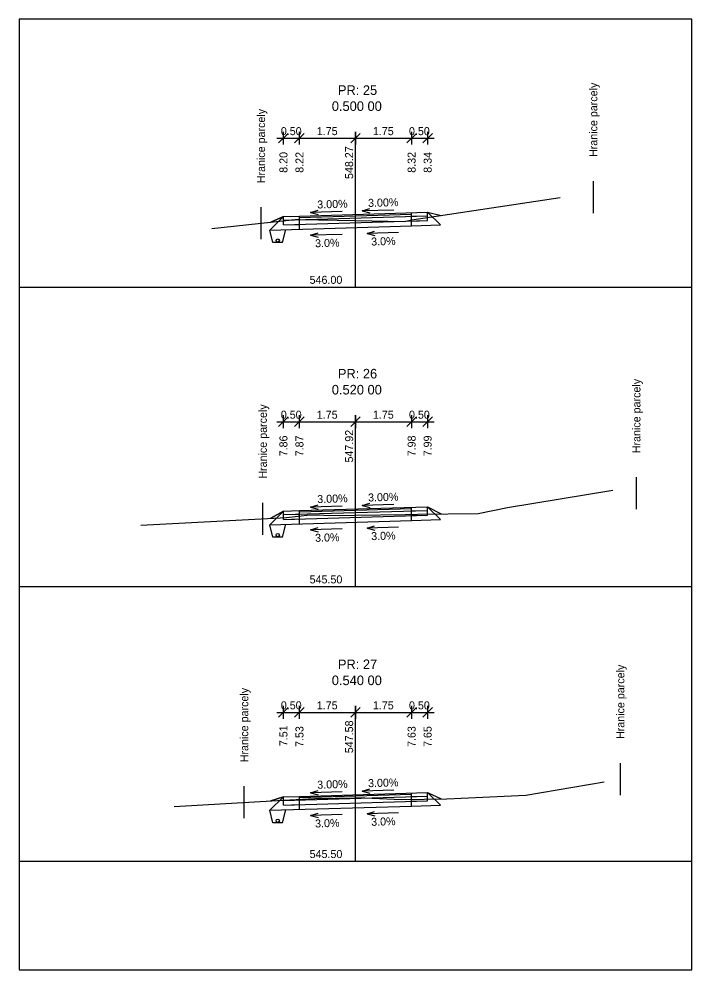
# Model space of a CAD drawing. Extents: x -603737 to -603383, y -1112154 to -1112124.
# Drawn here: x -603504.76 to -603483.76, y -1112153.84 to -1112124.14 of the extents above; entities that cross this region are included whole.
import ezdxf

# ---------------------------------------------------------------- set-up
doc = ezdxf.new("R2010")
doc.units = 0
for name, color, linetype in [('_křivky z hran', 7, 'Continuous'), ('_netisk', 7, 'Continuous'), ('C3D_Podsestava-Popis', 7, 'Continuous'), ('C3D_PP-Popisek', 7, 'Continuous'), ('C3D_PR', 7, 'Continuous'), ('C3D_ZPR', 7, 'Continuous'), ('Default', 7, 'Continuous'), ('konstrukce', 7, 'Continuous')]:
    doc.layers.add(name, color=color, linetype=linetype)

# ---------------------------------------------------------------- blocks, each defined once
blk = doc.blocks.new('_Oblique')
at = {"layer": 'Default'}
blk.add_line((-0.5, -0.5), (0.5, 0.5), dxfattribs=at)
blk = doc.blocks.new('AeccTickLine')
at = {"layer": 'Default'}
blk.add_line((0, 1), (0, -1), dxfattribs=at)

msp = doc.modelspace()

# ---------------------------------------------------------------- linework, layer by layer
at = {"layer": '_netisk'}
msp.add_lwpolyline([(-603504.762, -1112153.84), (-603483.762, -1112153.84), (-603483.762, -1112124.14), (-603504.762, -1112124.14)], close=True, dxfattribs=at)
at = {"layer": 'C3D_Podsestava-Popis'}
for p, q in [((-603496.712, -1112127.861), (-603494.262, -1112127.861)), ((-603494.262, -1112127.861), (-603491.812, -1112127.861)), ((-603494.262, -1112128.243), (-603494.262, -1112128.011)), ((-603496.712, -1112136.717), (-603494.262, -1112136.717)), ((-603494.262, -1112136.717), (-603491.812, -1112136.717)), ((-603494.262, -1112137.443), (-603494.262, -1112136.867)), ((-603496.712, -1112145.794), (-603494.262, -1112145.794)), ((-603494.262, -1112145.794), (-603491.812, -1112145.794)), ((-603494.262, -1112146.364), (-603494.262, -1112145.944))]:
    msp.add_line(p, q, dxfattribs=at)
at = {"layer": 'C3D_PP-Popisek'}
for p, q in [((-603495.665, -1112130.185), (-603495.428, -1112130.109)), ((-603494.681, -1112130.155), (-603495.665, -1112130.185)), ((-603494.054, -1112130.136), (-603493.817, -1112130.061)), ((-603493.07, -1112130.107), (-603494.054, -1112130.136)), ((-603494.054, -1112130.136), (-603493.813, -1112130.197)), ((-603495.665, -1112130.185), (-603495.424, -1112130.246)), ((-603495.665, -1112130.895), (-603495.428, -1112130.819)), ((-603494.681, -1112130.865), (-603495.665, -1112130.895)), ((-603495.665, -1112130.895), (-603495.424, -1112130.956)), ((-603493.9, -1112130.842), (-603493.664, -1112130.767)), ((-603492.917, -1112130.812), (-603493.9, -1112130.842)), ((-603493.9, -1112130.842), (-603493.66, -1112130.903)), ((-603495.665, -1112139.385), (-603495.428, -1112139.31)), ((-603494.681, -1112139.355), (-603495.665, -1112139.385)), ((-603494.054, -1112139.336), (-603493.817, -1112139.261)), ((-603493.07, -1112139.307), (-603494.054, -1112139.336)), ((-603494.054, -1112139.336), (-603493.813, -1112139.397)), ((-603495.665, -1112139.385), (-603495.424, -1112139.446)), ((-603495.665, -1112140.095), (-603495.428, -1112140.02)), ((-603494.681, -1112140.066), (-603495.665, -1112140.095)), ((-603495.665, -1112140.095), (-603495.424, -1112140.156)), ((-603493.9, -1112140.042), (-603493.664, -1112139.967)), ((-603492.917, -1112140.013), (-603493.9, -1112140.042)), ((-603493.9, -1112140.042), (-603493.66, -1112140.103)), ((-603495.665, -1112148.306), (-603495.428, -1112148.231)), ((-603494.681, -1112148.277), (-603495.665, -1112148.306)), ((-603494.054, -1112148.258), (-603493.817, -1112148.182)), ((-603493.07, -1112148.228), (-603494.054, -1112148.258)), ((-603494.054, -1112148.258), (-603493.813, -1112148.319)), ((-603495.665, -1112148.306), (-603495.424, -1112148.367)), ((-603495.665, -1112149.016), (-603495.428, -1112148.941)), ((-603494.681, -1112148.987), (-603495.665, -1112149.016)), ((-603495.665, -1112149.016), (-603495.424, -1112149.077)), ((-603493.9, -1112148.963), (-603493.664, -1112148.888)), ((-603492.917, -1112148.934), (-603493.9, -1112148.963)), ((-603493.9, -1112148.963), (-603493.66, -1112149.025))]:
    msp.add_line(p, q, dxfattribs=at)
at = {"layer": 'C3D_PR'}
for points in [[(-603498.742, -1112130.684), (-603496.141, -1112130.406), (-603496.078, -1112130.403), (-603495.984, -1112130.405), (-603494.262, -1112130.435), (-603492.741, -1112130.461), (-603492.507, -1112130.411), (-603487.876, -1112129.715)], [(-603500.963, -1112139.951), (-603496.414, -1112139.706), (-603495.686, -1112139.628), (-603494.81, -1112139.644), (-603494.262, -1112139.636), (-603492.714, -1112139.616), (-603492.321, -1112139.609), (-603490.432, -1112139.583), (-603489.523, -1112139.397), (-603489.523, -1112139.397), (-603489.522, -1112139.396), (-603486.233, -1112138.855)], [(-603499.917, -1112148.73), (-603496.692, -1112148.549), (-603495.532, -1112148.488), (-603494.262, -1112148.469), (-603493.974, -1112148.465), (-603492.824, -1112148.517), (-603491.407, -1112148.494), (-603488.95, -1112148.382), (-603486.506, -1112147.969)]]:
    msp.add_lwpolyline(points, dxfattribs=at)
at = {"layer": 'C3D_ZPR'}
for p, q in [((-603494.262, -1112132.511), (-603494.262, -1112128.011)), ((-603486.839, -1112130.2), (-603486.839, -1112129.2)), ((-603497.209, -1112131.02), (-603497.209, -1112130.02)), ((-603496.935, -1112130.733), (-603496.512, -1112130.31)), ((-603496.512, -1112130.31), (-603496.907, -1112130.488)), ((-603496.907, -1112130.488), (-603496.512, -1112130.31)), ((-603496.512, -1112130.42), (-603492.012, -1112130.285)), ((-603496.512, -1112130.31), (-603496.012, -1112130.295)), ((-603496.512, -1112130.57), (-603496.512, -1112130.31)), ((-603496.512, -1112130.57), (-603496.512, -1112130.31)), ((-603496.512, -1112130.42), (-603496.012, -1112130.405)), ((-603496.512, -1112130.57), (-603492.012, -1112130.435)), ((-603496.012, -1112130.295), (-603492.012, -1112130.175)), ((-603496.012, -1112130.335), (-603492.512, -1112130.23)), ((-603496.012, -1112130.705), (-603496.012, -1112130.295)), ((-603496.012, -1112130.405), (-603496.012, -1112130.335)), ((-603492.512, -1112130.23), (-603492.512, -1112130.19)), ((-603492.512, -1112130.6), (-603492.512, -1112130.19)), ((-603492.512, -1112130.3), (-603492.012, -1112130.285)), ((-603492.512, -1112130.45), (-603492.512, -1112130.3)), ((-603492.512, -1112130.45), (-603492.012, -1112130.435)), ((-603492.012, -1112130.435), (-603492.012, -1112130.175)), ((-603492.012, -1112130.435), (-603492.012, -1112130.175)), ((-603491.614, -1112130.573), (-603492.012, -1112130.175)), ((-603492.012, -1112130.175), (-603491.587, -1112130.273)), ((-603492.012, -1112130.175), (-603491.587, -1112130.273)), ((-603496.935, -1112130.733), (-603492.512, -1112130.6)), ((-603496.512, -1112130.57), (-603496.012, -1112130.555)), ((-603496.012, -1112130.705), (-603496.012, -1112130.555)), ((-603492.512, -1112130.6), (-603491.614, -1112130.573)), ((-603504.762, -1112132.511), (-603483.762, -1112132.511)), ((-603494.262, -1112141.867), (-603494.262, -1112136.867)), ((-603485.495, -1112139.452), (-603485.495, -1112138.452)), ((-603497.154, -1112140.246), (-603497.154, -1112139.246)), ((-603496.935, -1112139.933), (-603496.512, -1112139.51)), ((-603496.512, -1112139.51), (-603496.907, -1112139.732)), ((-603496.907, -1112139.732), (-603496.512, -1112139.51)), ((-603496.512, -1112139.62), (-603492.012, -1112139.485)), ((-603496.512, -1112139.51), (-603496.012, -1112139.495)), ((-603496.512, -1112139.77), (-603496.512, -1112139.51)), ((-603496.512, -1112139.77), (-603496.512, -1112139.51)), ((-603496.512, -1112139.62), (-603496.012, -1112139.605)), ((-603496.512, -1112139.77), (-603492.012, -1112139.635)), ((-603496.012, -1112139.495), (-603492.012, -1112139.375)), ((-603496.012, -1112139.535), (-603492.512, -1112139.43)), ((-603496.012, -1112139.905), (-603496.012, -1112139.495)), ((-603496.012, -1112139.605), (-603496.012, -1112139.535)), ((-603492.512, -1112139.43), (-603492.512, -1112139.39)), ((-603492.512, -1112139.8), (-603492.512, -1112139.39)), ((-603492.512, -1112139.5), (-603492.012, -1112139.485)), ((-603492.512, -1112139.65), (-603492.512, -1112139.5)), ((-603492.512, -1112139.65), (-603492.012, -1112139.635)), ((-603492.012, -1112139.635), (-603492.012, -1112139.375)), ((-603492.012, -1112139.635), (-603492.012, -1112139.375)), ((-603492.012, -1112139.375), (-603491.614, -1112139.773)), ((-603492.012, -1112139.375), (-603491.587, -1112139.599)), ((-603492.012, -1112139.375), (-603491.587, -1112139.599)), ((-603496.935, -1112139.933), (-603492.512, -1112139.8)), ((-603496.512, -1112139.77), (-603496.012, -1112139.755)), ((-603496.012, -1112139.905), (-603496.012, -1112139.755)), ((-603492.512, -1112139.8), (-603491.614, -1112139.773)), ((-603504.762, -1112141.867), (-603483.762, -1112141.867)), ((-603494.262, -1112150.444), (-603494.262, -1112145.944)), ((-603485.996, -1112148.377), (-603485.996, -1112147.377)), ((-603497.734, -1112149.103), (-603497.734, -1112148.103)), ((-603496.935, -1112148.854), (-603496.512, -1112148.432)), ((-603496.512, -1112148.432), (-603496.907, -1112148.561)), ((-603496.907, -1112148.561), (-603496.512, -1112148.432)), ((-603496.512, -1112148.542), (-603492.012, -1112148.407)), ((-603496.512, -1112148.432), (-603496.012, -1112148.417)), ((-603496.512, -1112148.692), (-603496.512, -1112148.432)), ((-603496.512, -1112148.692), (-603496.512, -1112148.432)), ((-603496.512, -1112148.542), (-603496.012, -1112148.527)), ((-603496.512, -1112148.692), (-603492.012, -1112148.557)), ((-603496.012, -1112148.417), (-603492.012, -1112148.297)), ((-603496.012, -1112148.457), (-603492.512, -1112148.352)), ((-603496.012, -1112148.827), (-603496.012, -1112148.417)), ((-603496.012, -1112148.527), (-603496.012, -1112148.457)), ((-603492.512, -1112148.352), (-603492.512, -1112148.312)), ((-603492.512, -1112148.722), (-603492.512, -1112148.312)), ((-603492.512, -1112148.422), (-603492.012, -1112148.407)), ((-603492.512, -1112148.572), (-603492.512, -1112148.422)), ((-603492.512, -1112148.572), (-603492.012, -1112148.557)), ((-603492.012, -1112148.557), (-603492.012, -1112148.297)), ((-603492.012, -1112148.557), (-603492.012, -1112148.297)), ((-603492.012, -1112148.297), (-603491.614, -1112148.695)), ((-603492.012, -1112148.297), (-603491.587, -1112148.497)), ((-603492.012, -1112148.297), (-603491.587, -1112148.497)), ((-603496.935, -1112148.854), (-603492.512, -1112148.722)), ((-603496.512, -1112148.692), (-603496.012, -1112148.677)), ((-603496.012, -1112148.827), (-603496.012, -1112148.677)), ((-603492.512, -1112148.722), (-603491.614, -1112148.695)), ((-603504.762, -1112150.444), (-603483.762, -1112150.444))]:
    msp.add_line(p, q, dxfattribs=at)
at = {"layer": 'konstrukce'}
for p, q in [((-603496.839, -1112131.118), (-603496.935, -1112130.733)), ((-603496.539, -1112131.118), (-603496.439, -1112130.718)), ((-603496.539, -1112131.118), (-603496.839, -1112131.118)), ((-603496.839, -1112140.318), (-603496.935, -1112139.933)), ((-603496.539, -1112140.318), (-603496.439, -1112139.918)), ((-603496.539, -1112140.318), (-603496.839, -1112140.318)), ((-603496.839, -1112149.24), (-603496.935, -1112148.854)), ((-603496.539, -1112149.24), (-603496.439, -1112148.84)), ((-603496.539, -1112149.24), (-603496.839, -1112149.24))]:
    msp.add_line(p, q, dxfattribs=at)
for centre in [(-603496.689, -1112131.058), (-603496.689, -1112140.258), (-603496.689, -1112149.18)]:
    msp.add_circle(centre, 0.05, dxfattribs=at)

# ---------------------------------------------------------------- block references
at = {"layer": '_křivky z hran', "rotation": 180}
for name, p, xscale, yscale in [('_Oblique', (-603496.512, -1112127.861), 0.3, 0.3), ('AeccTickLine', (-603496.512, -1112127.861), 0.2, 0.20000000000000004), ('_Oblique', (-603496.012, -1112127.861), 0.3, 0.3), ('AeccTickLine', (-603496.012, -1112127.861), 0.2, 0.20000000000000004), ('_Oblique', (-603494.262, -1112127.861), 0.3, 0.3), ('AeccTickLine', (-603494.262, -1112127.861), 0.2, 0.20000000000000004), ('_Oblique', (-603496.512, -1112136.717), 0.3, 0.3), ('AeccTickLine', (-603496.512, -1112136.717), 0.2, 0.20000000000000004), ('_Oblique', (-603496.012, -1112136.717), 0.3, 0.3), ('AeccTickLine', (-603496.012, -1112136.717), 0.2, 0.20000000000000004), ('_Oblique', (-603494.262, -1112136.717), 0.3, 0.3), ('AeccTickLine', (-603494.262, -1112136.717), 0.2, 0.20000000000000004), ('AeccTickLine', (-603496.512, -1112145.794), 0.2, 0.20000000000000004), ('AeccTickLine', (-603496.012, -1112145.794), 0.2, 0.20000000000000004), ('AeccTickLine', (-603494.262, -1112145.794), 0.2, 0.20000000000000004), ('_Oblique', (-603496.512, -1112145.794), 0.3, 0.3), ('_Oblique', (-603496.012, -1112145.794), 0.3, 0.3), ('_Oblique', (-603494.262, -1112145.794), 0.3, 0.3)]:
    msp.add_blockref(name, p, dxfattribs=dict(at, xscale=xscale, yscale=yscale))
at = {"layer": '_křivky z hran'}
for name, p, xscale, yscale in [('_Oblique', (-603494.262, -1112127.861), 0.3, 0.3), ('AeccTickLine', (-603494.262, -1112127.861), 0.2, 0.20000000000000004), ('_Oblique', (-603492.512, -1112127.861), 0.3, 0.3), ('AeccTickLine', (-603492.512, -1112127.861), 0.2, 0.20000000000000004), ('_Oblique', (-603492.012, -1112127.861), 0.3, 0.3), ('AeccTickLine', (-603492.012, -1112127.861), 0.2, 0.20000000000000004), ('_Oblique', (-603494.262, -1112136.717), 0.3, 0.3), ('AeccTickLine', (-603494.262, -1112136.717), 0.2, 0.20000000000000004), ('_Oblique', (-603492.512, -1112136.717), 0.3, 0.3), ('AeccTickLine', (-603492.512, -1112136.717), 0.2, 0.20000000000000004), ('_Oblique', (-603492.012, -1112136.717), 0.3, 0.3), ('AeccTickLine', (-603492.012, -1112136.717), 0.2, 0.20000000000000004), ('AeccTickLine', (-603494.262, -1112145.794), 0.2, 0.20000000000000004), ('AeccTickLine', (-603492.512, -1112145.794), 0.2, 0.20000000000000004), ('AeccTickLine', (-603492.012, -1112145.794), 0.2, 0.20000000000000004), ('_Oblique', (-603494.262, -1112145.794), 0.3, 0.3), ('_Oblique', (-603492.512, -1112145.794), 0.3, 0.3), ('_Oblique', (-603492.012, -1112145.794), 0.3, 0.3)]:
    msp.add_blockref(name, p, dxfattribs=dict(at, xscale=xscale, yscale=yscale))

# ---------------------------------------------------------------- texts
at = {"layer": 'C3D_Podsestava-Popis'}
for s, rotation, p in [('0.50', 360, (-603496.593, -1112127.767)), ('1.75', 360, (-603495.47, -1112127.767)), ('1.75', 360, (-603495.47, -1112127.767)), ('1.75', 360, (-603493.72, -1112127.767)), ('1.75', 360, (-603493.72, -1112127.767)), ('0.50', 360, (-603492.593, -1112127.767)), ('8.20', 90, (-603496.386, -1112128.943)), ('8.20', 90, (-603496.386, -1112128.943)), ('8.22', 90, (-603495.886, -1112128.942)), ('548.27', 90, (-603494.336, -1112129.137)), ('8.32', 90, (-603492.386, -1112128.942)), ('8.34', 90, (-603491.886, -1112128.943)), ('8.34', 90, (-603491.886, -1112128.943)), ('3.00%', 1.7184, (-603495.452, -1112130.059)), ('3.00%', 1.7184, (-603493.867, -1112130.01)), ('3.0%', 1.7184, (-603495.52, -1112131.27)), ('3.0%', 1.7184, (-603493.77, -1112131.217)), ('0.50', 360, (-603496.593, -1112136.623)), ('1.75', 360, (-603495.47, -1112136.623)), ('1.75', 360, (-603495.47, -1112136.623)), ('1.75', 360, (-603493.72, -1112136.623)), ('1.75', 360, (-603493.72, -1112136.623)), ('0.50', 360, (-603492.593, -1112136.623)), ('547.92', 90, (-603494.336, -1112137.992)), ('7.86', 90, (-603496.386, -1112137.799)), ('7.86', 90, (-603496.386, -1112137.799)), ('7.87', 90, (-603495.886, -1112137.799)), ('7.98', 90, (-603492.386, -1112137.799)), ('7.99', 90, (-603491.886, -1112137.799)), ('7.99', 90, (-603491.886, -1112137.799)), ('3.00%', 1.7184, (-603495.452, -1112139.259)), ('3.00%', 1.7184, (-603493.867, -1112139.21)), ('3.0%', 1.7184, (-603495.52, -1112140.47)), ('3.0%', 1.7184, (-603493.77, -1112140.417)), ('0.50', 360, (-603496.593, -1112145.7)), ('1.75', 360, (-603495.47, -1112145.7)), ('1.75', 360, (-603495.47, -1112145.7)), ('1.75', 360, (-603493.72, -1112145.7)), ('1.75', 360, (-603493.72, -1112145.7)), ('0.50', 360, (-603492.593, -1112145.7)), ('547.58', 90, (-603494.336, -1112147.07)), ('7.51', 90, (-603496.386, -1112146.851)), ('7.51', 90, (-603496.386, -1112146.851)), ('7.53', 90, (-603495.886, -1112146.875)), ('7.63', 90, (-603492.386, -1112146.875)), ('7.65', 90, (-603491.886, -1112146.876)), ('7.65', 90, (-603491.886, -1112146.876)), ('3.00%', 1.7184, (-603495.452, -1112148.18)), ('3.00%', 1.7184, (-603493.867, -1112148.132)), ('3.0%', 1.7184, (-603495.52, -1112149.391)), ('3.0%', 1.7184, (-603493.77, -1112149.339))]:
    msp.add_text(s, height=0.25, rotation=rotation, dxfattribs=at).set_placement(p)
at = {"layer": 'C3D_ZPR'}
for s, p in [('PR: 25', (-603494.812, -1112126.511)), ('0.500 00', (-603495.002, -1112127.011)), ('PR: 26', (-603494.812, -1112135.367)), ('0.520 00', (-603495.002, -1112135.867)), ('PR: 27', (-603494.812, -1112144.444)), ('0.540 00', (-603495.002, -1112144.944))]:
    msp.add_text(s, height=0.3, dxfattribs=at).set_placement(p)
for s, rotation, p in [('Hranice parcely', 90, (-603486.714, -1112128.45)), ('Hranice parcely', 90, (-603497.084, -1112129.27)), ('546.00', 360, (-603495.695, -1112132.411)), ('Hranice parcely', 90, (-603485.37, -1112137.702)), ('Hranice parcely', 90, (-603497.029, -1112138.496)), ('545.50', 360, (-603495.695, -1112141.767)), ('Hranice parcely', 90, (-603485.871, -1112146.627)), ('Hranice parcely', 90, (-603497.609, -1112147.353)), ('545.50', 360, (-603495.695, -1112150.344))]:
    msp.add_text(s, height=0.25, rotation=rotation, dxfattribs=at).set_placement(p)

doc.saveas('drawing.dxf')
